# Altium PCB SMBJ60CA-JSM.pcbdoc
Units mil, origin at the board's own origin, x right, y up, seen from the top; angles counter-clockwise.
Board outline 768.87 x 650 mil, 2 copper layers (Top Layer, Bottom Layer), stack 0 mil thick; 1 components, 0 nets, 2 pads, 0 vias.
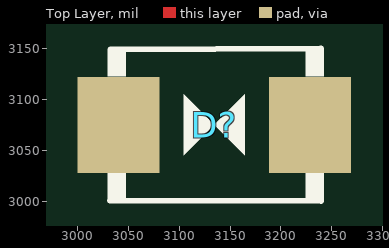
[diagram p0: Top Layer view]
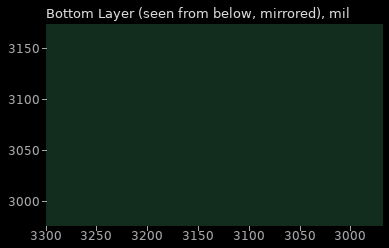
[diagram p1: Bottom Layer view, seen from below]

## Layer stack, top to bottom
Top Layer: signal copper (thickness not stored)
Bottom Layer: signal copper (thickness not stored)

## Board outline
3518.87,2750 2750,2750 2750,3400 3518.87,3400

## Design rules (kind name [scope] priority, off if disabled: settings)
PasteMaskExpansion "Paste Mask Expansion" [All] p1: expansion=0
SolderMaskExpansion "Solder Mask Expansion" [IsVia] p1: expansion=-1000 istentingtop=TRUE
SolderMaskExpansion "Solder Mask Expansion" [All] p2: expansion=2 istentingtop=FALSE

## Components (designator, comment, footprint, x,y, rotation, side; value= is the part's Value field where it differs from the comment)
D? "SMBJ60CA-JSM" SMB_L4.6-W3.6-LS5.3-BI 3134.43,3075 r0 top

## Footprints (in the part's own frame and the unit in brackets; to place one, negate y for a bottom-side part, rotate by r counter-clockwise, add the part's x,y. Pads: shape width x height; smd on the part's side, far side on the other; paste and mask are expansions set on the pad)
SMB_L4.6-W3.6-LS5.3-BI [mm]
  rect 2.047x2.4 smd: 1(-2.391,0) 2(2.391,0)
  silkscreen extent -2.67,-1.91 2.74,1.91

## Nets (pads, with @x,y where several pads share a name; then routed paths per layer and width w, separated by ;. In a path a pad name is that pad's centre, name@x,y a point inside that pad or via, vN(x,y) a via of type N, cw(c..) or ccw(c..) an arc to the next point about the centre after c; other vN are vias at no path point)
pads on no net: D?.1 D?.2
